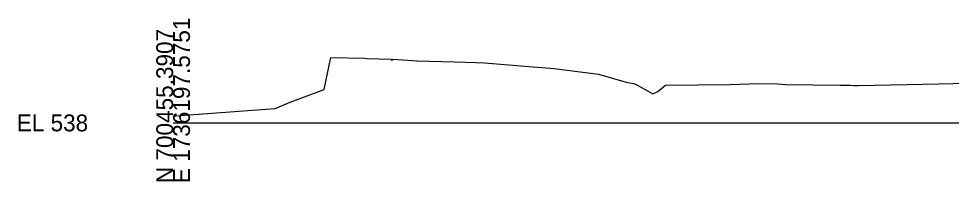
# Model space of a CAD drawing. Extents: x -26 to 803, y -10 to 646.
# Drawn here: x 474.3 to 629.4, y 390.3 to 417.3 of the extents above; entities that cross this region are included whole.
import ezdxf

# ---------------------------------------------------------------- set-up
doc = ezdxf.new("R2010")
doc.units = 0
for name, color, linetype in [('Default', 7, 'Continuous'), ('Exist Cross Section Cell', 7, 'Continuous'), ('Exist XS Ground Line', 7, 'Continuous')]:
    doc.layers.add(name, color=color, linetype=linetype)

msp = doc.modelspace()

# ---------------------------------------------------------------- linework, layer by layer
at = {"layer": 'Exist Cross Section Cell'}
msp.add_line((500, 400), (650, 400), dxfattribs=at)
at = {"layer": 'Exist XS Ground Line'}
for p, q in [((525.13, 405.55), (526.24, 410.87)), ((526.24, 410.87), (531.84, 410.73)), ((531.84, 410.73), (532.25, 410.7)), ((532.25, 410.7), (536.29, 410.57)), ((536.29, 410.57), (536.34, 410.44)), ((536.34, 410.44), (536.58, 410.56)), ((536.58, 410.56), (540.58, 410.31)), ((540.58, 410.31), (546.81, 410.13)), ((546.81, 410.13), (550.36, 410.03)), ((550.36, 410.03), (551.8, 410)), ((551.8, 410), (558.51, 409.44)), ((558.51, 409.44), (561.99, 409.15)), ((561.99, 409.15), (563.39, 409.01)), ((563.39, 409.01), (570.74, 408.08)), ((570.74, 408.08), (575.37, 406.75)), ((575.37, 406.75), (576.59, 406.53)), ((576.59, 406.53), (577, 406.35)), ((592.63, 406.38), (597.32, 406.52)), ((597.32, 406.52), (600.53, 406.48)), ((600.53, 406.48), (601.87, 406.37)), ((613.96, 406.21), (627.44, 406.5)), ((627.44, 406.5), (632.08, 406.58)), ((519.49, 403.44), (525.13, 405.55)), ((577, 406.35), (579.82, 404.82)), ((579.82, 404.82), (580.64, 405.24)), ((580.64, 405.24), (581.88, 406.24)), ((581.88, 406.24), (592.63, 406.38)), ((601.87, 406.37), (610.94, 406.24)), ((610.94, 406.24), (612.69, 406.24)), ((612.69, 406.24), (613.22, 406.23)), ((613.22, 406.23), (613.96, 406.21)), ((517, 402.41), (519.49, 403.44)), ((500.44, 401.16), (513.23, 402.09)), ((513.23, 402.09), (517, 402.41)), ((500, 401), (500.44, 401.16))]:
    msp.add_line(p, q, dxfattribs=at)

# ---------------------------------------------------------------- texts
at = {"layer": 'Default'}
msp.add_text('-', height=0.0001, dxfattribs=at).set_placement((500, 400))
msp.add_text('-', height=0.0001, dxfattribs=at).set_placement((500, 400))
at = {"layer": 'Exist Cross Section Cell'}
for s, p in [('E 1736197.5751', (502.8, 390)), ('N 700455.3907', (500, 390))]:
    msp.add_text(s, height=2.8, rotation=90, dxfattribs=at).set_placement(p)
msp.add_text('EL 538', height=2.8, dxfattribs=at).set_placement((474, 398.6))

doc.saveas('drawing.dxf')
